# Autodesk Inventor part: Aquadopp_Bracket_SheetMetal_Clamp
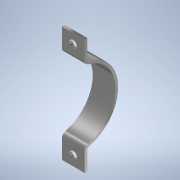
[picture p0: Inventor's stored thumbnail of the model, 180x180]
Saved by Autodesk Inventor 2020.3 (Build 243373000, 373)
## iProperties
Created: 2020-09
Part Number: Aquadopp_Bracket_SheetMetal_Clamp
Material: Stainless Steel
Document SubType Name: Sheet Metal
Designer: biggshj
Manufacturer: Standard
Standards Organization: Custom
Density: 8 g/cm^3
Sheet Metal Rule: Default_mm
Appearance: Semi-Polished
Mass: 93.0969 g
Surface Area: 90.1521 cm^2
Volume: 11.6371 cm^3
Author: biggshj
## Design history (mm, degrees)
node "Contour Flange1"
  sketch "Sketch2"
    geometry: L1 (0, 0)-(-5, 0); L2 (0, 38.678)-(0, 63.678); L3 (0, -38.678)-(0, -63.678); L4 (0, -89.149)-(0, 89.149) reference; A1 r 39 centre (-5, 0) between (0, -38.678) and (0, 38.678)
    constraints: 6 end point, 2 collinear, 2 point on circle, 2 vertical, 1 centre point, 1 coincident, 1 horizontal
    dimensions: "d0" = 5 distance of L1.start L1.end; "d1" = 39 radius of A1; "d2" = 25 distance of L2.start L2.end; "d3" = 25 distance of L3.start L3.end
sketch "Sketch3"
  geometry: L1 (0, 63.678)-(0, 10.678); L2 (0, 10.678)-(12.5, 10.678); C1 r 4.025 at (12.5, 10.678)
  constraints: 4 end point, 1 centre point, 1 coincident, 1 horizontal, 1 vertical
  dimensions: "d15" = 53 distance of L1.start L1.end; "d23" = 12.5 distance of L1.end L2.end; "d24" = 8.05 diameter of C1
extrude "Extrusion1" cut sketch "Sketch3" distance "d20" = 10; taper "d21" = 0 deg
mirror "Mirror1"
body "Solid1"
face "Plate1" dims "d4" = 3 (= Thickness), "d5" = 3 (= BendReliefWidth), "d6" = 1.5 (= BendReliefDepth), "d7" = 6 (= MinimumRemnant), "d8" = 3 (= TransitionRadius), "d9" = 25, "d10" = 3 (= BendRadius), "d11" = 3, "d12" = 12 (= CornerReliefSize), "d13" = 3 (= GapSize), "d14" = 3 (= JacobiRadiusSize), "SeamGap" = 0.01
bend "Bend1" dims "d4" = 3 (= Thickness), "d5" = 3 (= BendReliefWidth), "d6" = 1.5 (= BendReliefDepth), "d7" = 6 (= MinimumRemnant), "d8" = 3 (= TransitionRadius), "d10" = 3 (= BendRadius), "d11" = 3, "SeamGap" = 0.01
feature "Corner1" dims "d11" = 3, "d12" = 12 (= CornerReliefSize), "d13" = 3 (= GapSize), "d14" = 3 (= JacobiRadiusSize)
other parameters: "Thickness" = 3 (derived), "BendRadius" = 3 (= Thickness), "BendReliefWidth" = 3 (= Thickness), "BendReliefDepth" = 1.5 (= 0.5 x Thickness), "CornerReliefSize" = 12 (= 4 x Thickness), "MinimumRemnant" = 6 (= 2 x Thickness), "TransitionRadius" = 3 (= BendRadius), "JacobiRadiusSize" = 3 (= BendRadius), "GapSize" = 3 (= Thickness)
